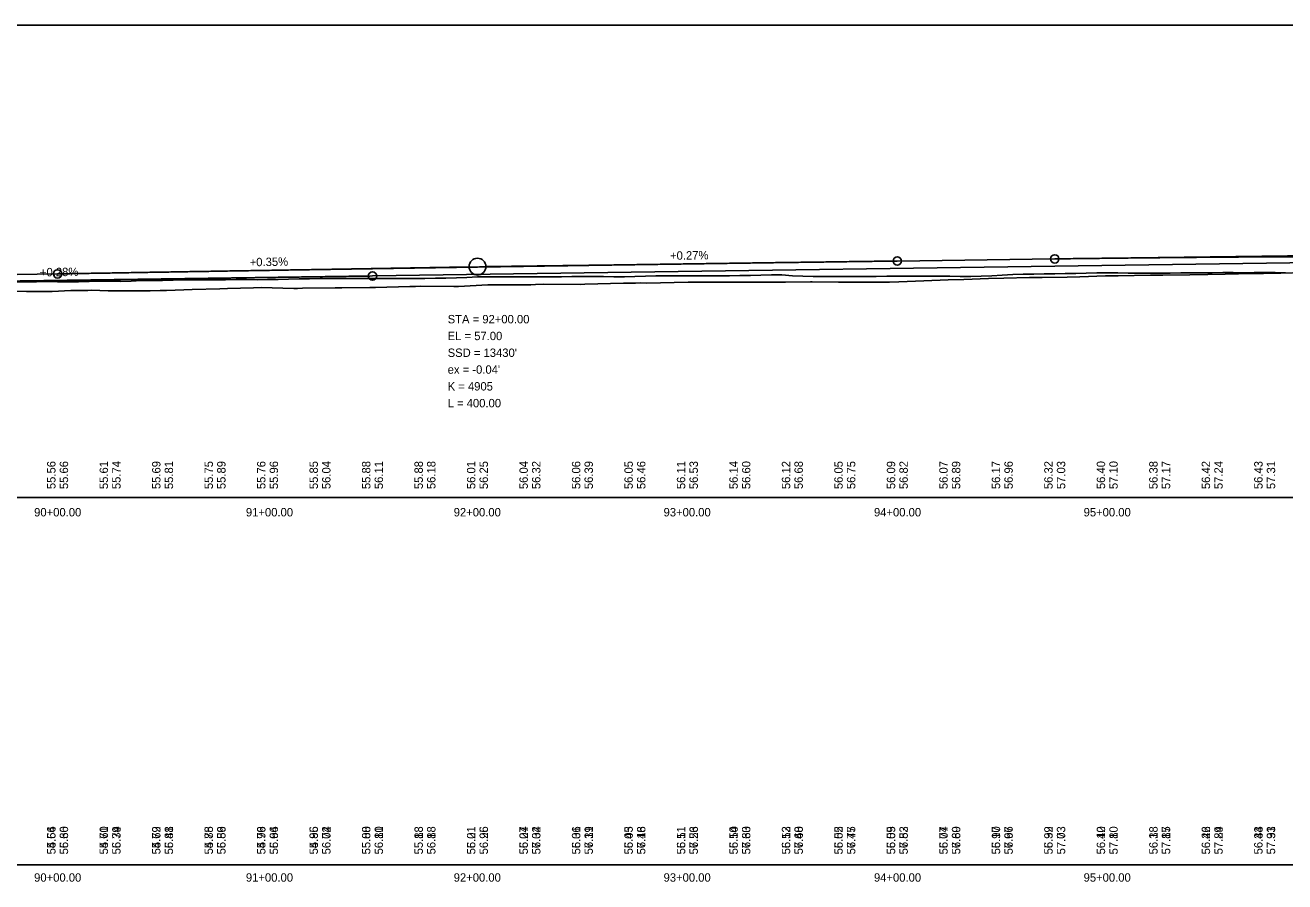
# Model space of a CAD drawing. Extents: x 3880794 to 3915434, y 287517 to 300173.
# Drawn here: x 3889523 to 3890123, y 297716 to 298124 of the extents above; entities that cross this region are included whole.
import ezdxf

# ---------------------------------------------------------------- set-up
doc = ezdxf.new("R2010")
doc.units = 0
for name, color, linetype in [('Level 1', 7, 'Continuous'), ('Level 2', 7, 'Continuous'), ('Level 30', 7, 'Continuous'), ('Level 31', 7, 'Continuous'), ('Level 32', 7, 'Continuous'), ('Level 62', 7, 'Continuous'), ('Level 63', 7, 'Continuous')]:
    doc.layers.add(name, color=color, linetype=linetype)

msp = doc.modelspace()

# ---------------------------------------------------------------- linework, layer by layer
at = {"layer": 'Level 1'}
for q in [(3890388.3, 298014.65), (3889442.3, 298001.25)]:
    msp.add_line((3889688.3, 298004.73), q, dxfattribs=at)
for points in [[(3889711.26, 297999.83), (3889727.05, 297999.74), (3889729.24, 297999.76), (3889743.3, 298000.49), (3889746.37, 298000.45), (3889763.69, 298000.57), (3889765.92, 298000.72), (3889769.6, 298000.76), (3889787.44, 298000.68), (3889789.4, 298000.83), (3889807.85, 298001.34), (3889811.01, 298001.35), (3889813.57, 298001.35), (3889815.89, 298001.4), (3889818.78, 298001.37), (3889838.75, 298001.75), (3889842.06, 298001.75), (3889845.8, 298001.74), (3889865.84, 298001.7), (3889869.24, 298001.71), (3889879.68, 298001.76), (3889885.07, 298001.8), (3889896.92, 298001.92), (3889897.75, 298001.93), (3889910.32, 298001.79), (3889915.94, 298001.79), (3889929.78, 298001.79), (3889934.53, 298001.77), (3889939.02, 298001.98), (3889950.88, 298002.47), (3889962.48, 298002.85), (3889970.06, 298003.09), (3889981.73, 298003.53), (3889989.12, 298003.73), (3890001.3, 298003.93), (3890007.29, 298004.07), (3890019.19, 298004.21), (3890025.33, 298004.32), (3890037.49, 298004.77), (3890043.53, 298004.87), (3890058.97, 298005.05), (3890064.77, 298005.07), (3890077.7, 298005.3), (3890086.15, 298005.45), (3890094.52, 298005.53), (3890100.85, 298005.67), (3890112.68, 298005.89), (3890120.96, 298006), (3890132.23, 298006.32)], [(3889514.54, 297997.55), (3889523.51, 297997.41), (3889524.89, 297997.29), (3889525.75, 297997.3), (3889531.46, 297997.27), (3889535.14, 297997.27), (3889535.66, 297997.27), (3889544.54, 297997.74), (3889552.64, 297997.84), (3889554.43, 297997.89), (3889562.44, 297997.67), (3889563.45, 297997.67), (3889565.03, 297997.65), (3889580.65, 297997.61), (3889582.47, 297997.6), (3889587.1, 297997.8), (3889588.41, 297997.79), (3889590.12, 297997.77), (3889598.45, 297998.15), (3889602.34, 297998.27), (3889615.51, 297998.64), (3889619.25, 297998.74), (3889631.6, 297999.09), (3889635.23, 297999.24), (3889650.84, 297998.78), (3889652.51, 297998.83), (3889655.01, 297998.88), (3889670.58, 297999.09), (3889673.76, 297999.1), (3889687.04, 297999.23), (3889689.67, 297999.2), (3889706.15, 297999.72), (3889708.76, 297999.75), (3889711.26, 297999.83)]]:
    msp.add_lwpolyline(points, dxfattribs=at)
msp.add_spline([(3889188.3, 297996.13), (3889198.3, 297996.33), (3889208.3, 297996.53), (3889218.3, 297996.73), (3889228.3, 297996.93), (3889238.3, 297997.13), (3889248.3, 297997.32), (3889258.3, 297997.52), (3889268.3, 297997.71), (3889278.3, 297997.9), (3889288.3, 297998.1), (3889298.3, 297998.28), (3889308.3, 297998.47), (3889318.3, 297998.66), (3889328.3, 297998.85), (3889338.3, 297999.03), (3889348.3, 297999.21), (3889358.3, 297999.4), (3889368.3, 297999.58), (3889378.3, 297999.76), (3889388.3, 297999.94), (3889398.3, 298000.11), (3889408.3, 298000.29), (3889418.3, 298000.47), (3889428.3, 298000.64), (3889438.3, 298000.81), (3889448.3, 298000.98), (3889458.3, 298001.15), (3889468.3, 298001.32), (3889478.3, 298001.49), (3889488.3, 298001.66), (3889498.3, 298001.82), (3889508.3, 298001.99), (3889518.3, 298002.15), (3889528.3, 298002.31), (3889538.3, 298002.47), (3889548.3, 298002.63), (3889558.3, 298002.79), (3889568.3, 298002.95), (3889578.3, 298003.1), (3889588.3, 298003.26), (3889598.3, 298003.41), (3889608.3, 298003.56), (3889618.3, 298003.71), (3889628.3, 298003.86), (3889638.3, 298004.01), (3889648.3, 298004.16), (3889658.3, 298004.3), (3889668.3, 298004.45), (3889678.3, 298004.59), (3889688.3, 298004.73)], degree=3, dxfattribs=at)
at = {"layer": 'Level 2'}
for p, q in [((3889938.3, 298011.86), (3889742.3, 298009.24)), ((3889938.3, 298011.86), (3890013.3, 298012.86)), ((3890013.3, 298012.86), (3890259.3, 298016.14)), ((3888781.3, 297992.53), (3889538.3, 298005.71)), ((3889538.3, 298005.71), (3889734.3, 298009.12))]:
    msp.add_line(p, q, dxfattribs=at)
for points in [[(3889538.3, 298001.98), (3889543.3, 298001.94), (3889548.3, 298001.94), (3889553.3, 298002.12), (3889558.3, 298002.18), (3889563.3, 298002.24), (3889568.3, 298002.15), (3889573.3, 298002.29), (3889578.3, 298002.51), (3889583.3, 298002.62), (3889588.3, 298002.65), (3889593.3, 298002.73), (3889598.3, 298002.81), (3889603.3, 298002.85), (3889608.3, 298002.9), (3889613.3, 298002.92), (3889618.3, 298002.96), (3889623.3, 298003.04), (3889628.3, 298002.98), (3889633.3, 298002.92), (3889638.3, 298003.01), (3889643.3, 298003.12), (3889648.3, 298003.23), (3889653.3, 298003.32), (3889658.3, 298003.36), (3889663.3, 298003.46), (3889668.3, 298003.48), (3889673.3, 298003.51), (3889678.3, 298003.59), (3889683.3, 298003.58), (3889688.3, 298003.57), (3889693.3, 298003.5), (3889698.3, 298003.47), (3889703.3, 298003.48), (3889708.3, 298003.53), (3889713.3, 298003.57), (3889718.3, 298003.61), (3889723.3, 298003.73), (3889728.3, 298003.91), (3889733.3, 298004.08), (3889738.3, 298004.26), (3889743.3, 298004.3), (3889748.3, 298004.28), (3889753.3, 298004.28), (3889758.3, 298004.33), (3889763.3, 298004.37), (3889768.3, 298004.35), (3889773.3, 298004.34), (3889778.3, 298004.35), (3889783.3, 298004.42), (3889788.3, 298004.47), (3889793.3, 298004.46), (3889798.3, 298004.4), (3889803.3, 298004.35), (3889808.3, 298004.34), (3889813.3, 298004.42), (3889818.3, 298004.59), (3889823.3, 298004.73), (3889828.3, 298004.82), (3889833.3, 298004.78), (3889838.3, 298004.73), (3889843.3, 298004.72), (3889848.3, 298004.73), (3889853.3, 298004.76), (3889858.3, 298004.84), (3889863.3, 298004.9), (3889868.3, 298004.96), (3889873.3, 298005.08), (3889878.3, 298005.21), (3889883.3, 298005.24), (3889888.3, 298004.81), (3889893.3, 298004.67), (3889898.3, 298004.5), (3889903.3, 298004.44), (3889908.3, 298004.43), (3889913.3, 298004.44), (3889918.3, 298004.45), (3889923.3, 298004.48), (3889928.3, 298004.53), (3889933.3, 298004.59), (3889938.3, 298004.64), (3889943.3, 298004.68), (3889948.3, 298004.67), (3889953.3, 298004.61), (3889958.3, 298004.59), (3889963.3, 298004.56), (3889968.3, 298004.53), (3889973.3, 298004.54), (3889978.3, 298004.65), (3889983.3, 298004.84), (3889988.3, 298005.06), (3889993.3, 298005.38), (3889998.3, 298005.52), (3890003.3, 298005.61), (3890008.3, 298005.71), (3890013.3, 298005.79), (3890018.3, 298005.88), (3890023.3, 298005.98), (3890028.3, 298006.08), (3890033.3, 298006.17), (3890038.3, 298006.18)], [(3890038.3, 298006.18), (3890043.3, 298006.16), (3890048.3, 298006.14), (3890053.3, 298006.13), (3890058.3, 298006.1), (3890063.3, 298006.08), (3890068.3, 298006.12), (3890073.3, 298006.17), (3890078.3, 298006.21), (3890083.3, 298006.25), (3890088.3, 298006.3), (3890093.3, 298006.32), (3890098.3, 298006.31), (3890103.3, 298006.3), (3890108.3, 298006.31), (3890113.3, 298006.32), (3890118.3, 298006.33), (3890123.3, 298006.3)], [(3889518.3, 298001.75), (3889523.3, 298001.86), (3889528.3, 298001.98), (3889533.3, 298002.02), (3889538.3, 298001.98)]]:
    msp.add_lwpolyline(points, dxfattribs=at)
for centre, radius in [((3889738.3, 298009.19), 4), ((3889938.3, 298011.86), 2), ((3890013.3, 298012.86), 2), ((3889538.3, 298005.71), 2)]:
    msp.add_circle(centre, radius, dxfattribs=at)
for points in [[(3889538.3, 298005.71), (3889546.3, 298005.85), (3889554.3, 298005.99), (3889562.3, 298006.12), (3889570.3, 298006.26), (3889578.3, 298006.4), (3889586.3, 298006.53), (3889594.3, 298006.67), (3889602.3, 298006.8), (3889610.3, 298006.93), (3889618.3, 298007.07), (3889626.3, 298007.2), (3889634.3, 298007.33), (3889642.3, 298007.46), (3889650.3, 298007.59), (3889658.3, 298007.72), (3889666.3, 298007.85), (3889674.3, 298007.98), (3889682.3, 298008.11), (3889690.3, 298008.24), (3889698.3, 298008.36), (3889706.3, 298008.49), (3889714.3, 298008.61), (3889722.3, 298008.74), (3889730.3, 298008.86), (3889738.3, 298008.99), (3889746.3, 298009.11), (3889754.3, 298009.23), (3889762.3, 298009.35), (3889770.3, 298009.47), (3889778.3, 298009.59), (3889786.3, 298009.71), (3889794.3, 298009.83), (3889802.3, 298009.95), (3889810.3, 298010.07), (3889818.3, 298010.18), (3889826.3, 298010.3), (3889834.3, 298010.41), (3889842.3, 298010.53), (3889850.3, 298010.64), (3889858.3, 298010.76), (3889866.3, 298010.87), (3889874.3, 298010.98), (3889882.3, 298011.1), (3889890.3, 298011.21), (3889898.3, 298011.32), (3889906.3, 298011.42), (3889914.3, 298011.53), (3889922.3, 298011.64), (3889930.3, 298011.75), (3889938.3, 298011.86)], [(3890013.3, 298012.86), (3890023.3, 298012.99), (3890033.3, 298013.11), (3890043.3, 298013.23), (3890053.3, 298013.34), (3890063.3, 298013.44), (3890073.3, 298013.53), (3890083.3, 298013.62), (3890093.3, 298013.7), (3890103.3, 298013.78), (3890113.3, 298013.84), (3890123.3, 298013.9), (3890133.3, 298013.96), (3890143.3, 298014), (3890153.3, 298014.04), (3890163.3, 298014.08), (3890173.3, 298014.1), (3890183.3, 298014.12), (3890193.3, 298014.13), (3890203.3, 298014.14), (3890213.3, 298014.13), (3890223.3, 298014.12), (3890233.3, 298014.11), (3890243.3, 298014.09), (3890253.3, 298014.06), (3890263.3, 298014.02), (3890273.3, 298013.98), (3890283.3, 298013.92), (3890293.3, 298013.87), (3890303.3, 298013.8), (3890313.3, 298013.73), (3890323.3, 298013.65), (3890333.3, 298013.57), (3890343.3, 298013.47), (3890353.3, 298013.37), (3890363.3, 298013.27), (3890373.3, 298013.15), (3890383.3, 298013.03), (3890393.3, 298012.91), (3890403.3, 298012.77), (3890413.3, 298012.63), (3890423.3, 298012.48), (3890433.3, 298012.33), (3890443.3, 298012.17), (3890453.3, 298012), (3890463.3, 298011.82), (3890473.3, 298011.64), (3890483.3, 298011.45), (3890493.3, 298011.25), (3890503.3, 298011.05), (3890513.3, 298010.84)]]:
    msp.add_spline(points, degree=3, dxfattribs=at)
at = {"layer": 'Level 31'}
msp.add_circle((3889688.3, 298004.73), 2, dxfattribs=at)
at = {"layer": 'Level 62'}
msp.add_lwpolyline([(3889438.3, 297899.19), (3890138.3, 297899.19), (3890138.3, 298124.19), (3889438.3, 298124.19)], close=True, dxfattribs=at)
msp.add_lwpolyline([(3889438.3, 297899.19), (3890138.3, 297899.19), (3890138.3, 298124.19), (3889438.3, 298124.19)], close=True, dxfattribs=at)
at = {"layer": 'Level 63'}
msp.add_line((3881538.3, 297724.19), (3896411.35, 297724.19), dxfattribs=at)

# ---------------------------------------------------------------- texts
at = {"layer": 'Level 2'}
for s, rotation, p in [('+0.35%', 0.99748, (3889629.84, 298009.3)), ('+0.27%', 0.7639, (3889830.07, 298012.41))]:
    msp.add_text(s, height=4, rotation=rotation, dxfattribs=at).set_placement(p)
for s, p in [('STA = 92+00.00', (3889724.11, 297982.16)), ('EL = 57.00', (3889724.11, 297974.16)), ("SSD = 13430'", (3889724.11, 297966.16)), ("ex = -0.04'", (3889724.11, 297958.16)), ('K = 4905', (3889724.11, 297950.16)), ('L = 400.00', (3889724.11, 297942.16))]:
    msp.add_text(s, height=4, dxfattribs=at).set_placement(p)
at = {"layer": 'Level 30'}
for s, p in [('90+00.00', (3889527.12, 297890.19)), ('90+00.00', (3889527.12, 297890.19)), ('91+00.00', (3889628, 297890.19)), ('91+00.00', (3889628, 297890.19)), ('92+00.00', (3889726.99, 297890.19)), ('92+00.00', (3889726.99, 297890.19)), ('93+00.00', (3889826.96, 297890.19)), ('93+00.00', (3889826.96, 297890.19)), ('94+00.00', (3889927.18, 297890.19)), ('94+00.00', (3889927.18, 297890.19)), ('95+00.00', (3890027.05, 297890.19)), ('95+00.00', (3890027.05, 297890.19)), ('90+00.00', (3889527.12, 297716.19)), ('90+00.00', (3889527.12, 297716.19)), ('91+00.00', (3889628, 297716.19)), ('91+00.00', (3889628, 297716.19)), ('92+00.00', (3889726.99, 297716.19)), ('92+00.00', (3889726.99, 297716.19)), ('93+00.00', (3889826.96, 297716.19)), ('93+00.00', (3889826.96, 297716.19)), ('94+00.00', (3889927.18, 297716.19)), ('94+00.00', (3889927.18, 297716.19)), ('95+00.00', (3890027.05, 297716.19)), ('95+00.00', (3890027.05, 297716.19))]:
    msp.add_text(s, height=4, dxfattribs=at).set_placement(p)
at = {"layer": 'Level 31'}
for s, rotation, p in [('+0.28%', 0.81164, (3889529.91, 298004.49)), ('55.66', 90, (3889543.3, 297903.19)), ('55.74', 90, (3889568.3, 297903.19)), ('55.81', 90, (3889593.3, 297903.19)), ('55.89', 90, (3889618.3, 297903.19)), ('55.96', 90, (3889643.3, 297903.19)), ('56.04', 90, (3889668.3, 297903.19)), ('56.11', 90, (3889693.3, 297903.19)), ('56.18', 90, (3889718.3, 297903.19)), ('56.25', 90, (3889743.3, 297903.19)), ('56.32', 90, (3889768.3, 297903.19)), ('56.39', 90, (3889793.3, 297903.19)), ('56.46', 90, (3889818.3, 297903.19)), ('56.53', 90, (3889843.3, 297903.19)), ('56.60', 90, (3889868.3, 297903.19)), ('56.68', 90, (3889893.3, 297903.19)), ('56.75', 90, (3889918.3, 297903.19)), ('56.82', 90, (3889943.3, 297903.19)), ('56.89', 90, (3889968.3, 297903.19)), ('56.96', 90, (3889993.3, 297903.19)), ('57.03', 90, (3890018.3, 297903.19)), ('57.10', 90, (3890043.3, 297903.19)), ('57.17', 90, (3890068.3, 297903.19)), ('57.24', 90, (3890093.3, 297903.19)), ('57.31', 90, (3890118.3, 297903.19)), ('54.64', 90, (3889537.3, 297729.19)), ('55.66', 90, (3889543.3, 297729.19)), ('54.70', 90, (3889562.3, 297729.19)), ('55.74', 90, (3889568.3, 297729.19)), ('54.72', 90, (3889587.3, 297729.19)), ('55.81', 90, (3889593.3, 297729.19)), ('54.88', 90, (3889612.3, 297729.19)), ('55.89', 90, (3889618.3, 297729.19)), ('54.99', 90, (3889637.3, 297729.19)), ('55.96', 90, (3889643.3, 297729.19)), ('54.96', 90, (3889662.3, 297729.19)), ('56.04', 90, (3889668.3, 297729.19)), ('55.00', 90, (3889687.3, 297729.19)), ('56.11', 90, (3889693.3, 297729.19)), ('55.13', 90, (3889712.3, 297729.19)), ('56.18', 90, (3889718.3, 297729.19)), ('55.21', 90, (3889737.3, 297729.19)), ('56.25', 90, (3889743.3, 297729.19)), ('55.27', 90, (3889762.3, 297729.19)), ('56.32', 90, (3889768.3, 297729.19)), ('55.31', 90, (3889787.3, 297729.19)), ('56.39', 90, (3889793.3, 297729.19)), ('55.43', 90, (3889812.3, 297729.19)), ('56.46', 90, (3889818.3, 297729.19)), ('55.51', 90, (3889837.3, 297729.19)), ('56.53', 90, (3889843.3, 297729.19)), ('55.50', 90, (3889862.3, 297729.19)), ('56.60', 90, (3889868.3, 297729.19)), ('55.53', 90, (3889887.3, 297729.19)), ('56.68', 90, (3889893.3, 297729.19)), ('55.52', 90, (3889912.3, 297729.19)), ('56.75', 90, (3889918.3, 297729.19)), ('55.55', 90, (3889937.3, 297729.19)), ('56.82', 90, (3889943.3, 297729.19)), ('55.74', 90, (3889962.3, 297729.19)), ('56.89', 90, (3889968.3, 297729.19)), ('55.90', 90, (3889987.3, 297729.19)), ('56.96', 90, (3889993.3, 297729.19)), ('55.99', 90, (3890012.3, 297729.19)), ('57.03', 90, (3890018.3, 297729.19)), ('56.12', 90, (3890037.3, 297729.19)), ('57.10', 90, (3890043.3, 297729.19)), ('56.18', 90, (3890062.3, 297729.19)), ('57.17', 90, (3890068.3, 297729.19)), ('56.26', 90, (3890087.3, 297729.19)), ('57.24', 90, (3890093.3, 297729.19)), ('56.34', 90, (3890112.3, 297729.19)), ('57.31', 90, (3890118.3, 297729.19))]:
    msp.add_text(s, height=4, rotation=rotation, dxfattribs=at).set_placement(p)
at = {"layer": 'Level 32'}
for s, p in [('55.56', (3889537.3, 297903.19)), ('55.61', (3889562.3, 297903.19)), ('55.69', (3889587.3, 297903.19)), ('55.75', (3889612.3, 297903.19)), ('55.76', (3889637.3, 297903.19)), ('55.85', (3889662.3, 297903.19)), ('55.88', (3889687.3, 297903.19)), ('55.88', (3889712.3, 297903.19)), ('56.01', (3889737.3, 297903.19)), ('56.04', (3889762.3, 297903.19)), ('56.06', (3889787.3, 297903.19)), ('56.05', (3889812.3, 297903.19)), ('56.11', (3889837.3, 297903.19)), ('56.14', (3889862.3, 297903.19)), ('56.12', (3889887.3, 297903.19)), ('56.05', (3889912.3, 297903.19)), ('56.09', (3889937.3, 297903.19)), ('56.07', (3889962.3, 297903.19)), ('56.17', (3889987.3, 297903.19)), ('56.32', (3890012.3, 297903.19)), ('56.40', (3890037.3, 297903.19)), ('56.38', (3890062.3, 297903.19)), ('56.42', (3890087.3, 297903.19)), ('56.43', (3890112.3, 297903.19)), ('55.56', (3889537.3, 297729.19)), ('56.30', (3889543.3, 297729.19)), ('55.61', (3889562.3, 297729.19)), ('56.39', (3889568.3, 297729.19)), ('55.69', (3889587.3, 297729.19)), ('56.48', (3889593.3, 297729.19)), ('55.75', (3889612.3, 297729.19)), ('56.56', (3889618.3, 297729.19)), ('55.76', (3889637.3, 297729.19)), ('56.64', (3889643.3, 297729.19)), ('55.85', (3889662.3, 297729.19)), ('56.72', (3889668.3, 297729.19)), ('55.88', (3889687.3, 297729.19)), ('56.80', (3889693.3, 297729.19)), ('55.88', (3889712.3, 297729.19)), ('56.88', (3889718.3, 297729.19)), ('56.01', (3889737.3, 297729.19)), ('56.96', (3889743.3, 297729.19)), ('56.04', (3889762.3, 297729.19)), ('57.04', (3889768.3, 297729.19)), ('56.06', (3889787.3, 297729.19)), ('57.11', (3889793.3, 297729.19)), ('56.05', (3889812.3, 297729.19)), ('57.18', (3889818.3, 297729.19)), ('56.11', (3889837.3, 297729.19)), ('57.26', (3889843.3, 297729.19)), ('56.14', (3889862.3, 297729.19)), ('57.33', (3889868.3, 297729.19)), ('56.12', (3889887.3, 297729.19)), ('57.40', (3889893.3, 297729.19)), ('56.05', (3889912.3, 297729.19)), ('57.47', (3889918.3, 297729.19)), ('56.09', (3889937.3, 297729.19)), ('57.53', (3889943.3, 297729.19)), ('56.07', (3889962.3, 297729.19)), ('57.60', (3889968.3, 297729.19)), ('56.17', (3889987.3, 297729.19)), ('57.67', (3889993.3, 297729.19)), ('56.32', (3890012.3, 297729.19)), ('57.73', (3890018.3, 297729.19)), ('56.40', (3890037.3, 297729.19)), ('57.80', (3890043.3, 297729.19)), ('56.38', (3890062.3, 297729.19)), ('57.85', (3890068.3, 297729.19)), ('56.42', (3890087.3, 297729.19)), ('57.89', (3890093.3, 297729.19)), ('56.43', (3890112.3, 297729.19)), ('57.93', (3890118.3, 297729.19))]:
    msp.add_text(s, height=4, rotation=90, dxfattribs=at).set_placement(p)

doc.saveas('drawing.dxf')
